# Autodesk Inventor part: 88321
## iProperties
Created: 2007-10
Part Number: 88321
Material: 3.2315.71 AlMgSi1 F28
Description: Zentrierring (A2/FPM) DN 10 KF
Document SubType Name: Modellieren
Designer: TMT
Manufacturer: Standard
Standards Organization: Custom
Density: 1 g/cm^3
Vendor: LEYBOLD
Author: TMT
Comments: LEYBOLD
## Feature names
1. Extrusion2
2. Bohrung1 [Hole]
3. Umdrehung1 [Revolution]
4. Umdrehung2 [Revolution]
5. Fase1 [Chamfer]
